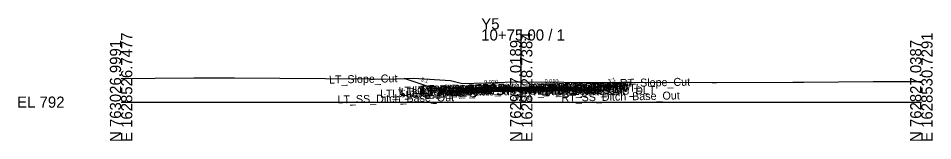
# Model space of a CAD drawing. Extents: x -26 to 203, y -10 to 6017.
# Drawn here: x -25.7 to 202.8, y 1490.3 to 1521.1 of the extents above; entities that cross this region are included whole.
import ezdxf

# ---------------------------------------------------------------- set-up
doc = ezdxf.new("R2010")
doc.units = 0
for name, color, linetype in [('Default', 7, 'Continuous'), ('Exist Cross Section Cell', 7, 'Continuous'), ('Exist XS Center Line Elevation Label', 7, 'Continuous'), ('Exist XS Ground Line', 7, 'Continuous'), ('Prop CMT Concrete Structures', 7, 'Continuous'), ('Prop CMT Pvmt Course 1', 7, 'Continuous'), ('Prop CMT Pvmt Course 2', 7, 'Continuous'), ('Prop CMT Pvmt Course 2 Wedge', 7, 'Continuous'), ('Prop CMT Pvmt Course 3', 7, 'Continuous'), ('Prop CMT Pvmt Course 3 Wedge', 7, 'Continuous'), ('Prop CMT Pvmt Surface', 7, 'Continuous'), ('Prop CMT Pvmt Surface Shoulder', 7, 'Continuous'), ('Prop CMT Pvmt Wedge Surface 2', 7, 'Continuous'), ('Prop CMT Pvmt Wedge Surface 3', 7, 'Continuous'), ('Prop CMT Shld Paved Course 1', 7, 'Continuous'), ('Prop CMT Shld Paved Course 2', 7, 'Continuous'), ('Prop CMT Shld Paved Course 3', 7, 'Continuous'), ('Prop CMT Slope Grass', 7, 'Continuous'), ('Prop CMT Subgrade Earthwork', 7, 'Continuous'), ('Prop XS SE Text', 7, 'Continuous'), ('Prop XS Side Slope Text', 7, 'Continuous'), ('Scratch_Level_0', 7, 'Continuous')]:
    doc.layers.add(name, color=color, linetype=linetype)

msp = doc.modelspace()

# ---------------------------------------------------------------- linework, layer by layer
at = {"layer": 'Exist Cross Section Cell'}
for p, q in [((100, 1500), (100, 1518.25)), ((0, 1500), (100, 1500)), ((100, 1500), (200, 1500))]:
    msp.add_line(p, q, dxfattribs=at)
at = {"layer": 'Exist XS Ground Line'}
msp.add_lwpolyline([(0, 1505.93), (8.51, 1505.99), (18.21, 1506.08), (28.36, 1506.08), (62.45, 1505.86), (66.74, 1505.79), (73.06, 1506.01), (82.35, 1505.39), (85.34, 1504.64), (91.08, 1504.83), (98.44, 1505.07), (100, 1505.06), (110.61, 1504.97), (114.33, 1504.92), (115.88, 1504.95), (124.96, 1505.01), (127.4, 1505.02), (147.74, 1504.96), (148.83, 1504.96), (167.92, 1504.98), (170.61, 1504.99), (187.96, 1505.15), (191.45, 1505.16), (200, 1505.2)], dxfattribs=at)
at = {"layer": 'Prop CMT Concrete Structures'}
for points in [[(115, 1503.29), (115, 1503.87)], [(117, 1503.87), (117, 1503.29), (115, 1503.29)], [(115, 1503.87), (116, 1503.79), (117, 1503.87)], [(83, 1503.42), (83, 1502.84), (85, 1502.84)], [(85, 1503.42), (84, 1503.34), (83, 1503.42)], [(85, 1502.84), (85, 1503.42)]]:
    msp.add_lwpolyline(points, dxfattribs=at)
at = {"layer": 'Prop CMT Pvmt Course 1'}
for points in [[(100, 1503.72), (115, 1503.87)], [(100, 1503.72), (114.33, 1503.86)], [(115, 1503.87), (115, 1503.62)], [(100, 1503.72), (85, 1503.42)], [(85, 1503.17), (100, 1503.47)], [(85, 1503.42), (85, 1503.17)], [(100, 1503.72), (85.32, 1503.43)], [(100, 1503.59), (100, 1503.72)], [(100, 1503.47), (100, 1503.72)], [(100, 1503.59), (100, 1503.72)], [(100, 1503.47), (100, 1503.72)], [(115, 1503.62), (100, 1503.47)]]:
    msp.add_lwpolyline(points, dxfattribs=at)
at = {"layer": 'Prop CMT Pvmt Course 2'}
for points in [[(100, 1503.47), (85, 1503.17)], [(85, 1503.17), (85, 1502.84)], [(85, 1502.84), (100, 1503.14)], [(100, 1503.47), (115, 1503.62)], [(100, 1503.14), (100, 1503.47)], [(100, 1503.14), (100, 1503.47)], [(115, 1503.29), (100, 1503.14)], [(115, 1503.62), (115, 1503.29)]]:
    msp.add_lwpolyline(points, dxfattribs=at)
at = {"layer": 'Prop CMT Pvmt Course 2 Wedge'}
for points in [[(100, 1503.47), (85.32, 1503.18)], [(100, 1503.47), (114.33, 1503.61)]]:
    msp.add_lwpolyline(points, dxfattribs=at)
at = {"layer": 'Prop CMT Pvmt Course 3'}
msp.add_line((117, 1503.29), (117.5, 1503.29), dxfattribs=at)
for points in [[(100, 1503.14), (85, 1502.84)], [(85, 1502.84), (85, 1502.5)], [(85, 1502.5), (100, 1502.8)], [(100, 1503.14), (115, 1503.29)], [(100, 1502.8), (100, 1503.14)], [(100, 1502.8), (100, 1503.14)], [(115, 1502.95), (100, 1502.8)], [(115, 1503.29), (115, 1502.95)]]:
    msp.add_lwpolyline(points, dxfattribs=at)
at = {"layer": 'Prop CMT Pvmt Course 3 Wedge'}
for points in [[(100, 1503.14), (85.32, 1502.84)], [(100, 1503.14), (114.33, 1503.28)]]:
    msp.add_lwpolyline(points, dxfattribs=at)
at = {"layer": 'Prop CMT Pvmt Surface'}
for points in [[(100, 1503.72), (115, 1503.87)], [(100, 1503.72), (114.33, 1503.86)], [(100, 1503.72), (85, 1503.42)], [(100, 1503.72), (85.32, 1503.43)]]:
    msp.add_lwpolyline(points, dxfattribs=at)
at = {"layer": 'Prop CMT Pvmt Surface Shoulder'}
for points in [[(115, 1503.87), (115, 1503.87)], [(85, 1503.42), (85, 1503.42)]]:
    msp.add_lwpolyline(points, dxfattribs=at)
at = {"layer": 'Prop CMT Pvmt Wedge Surface 2'}
for points in [[(100, 1503.47), (85.32, 1503.18)], [(100, 1503.47), (100, 1503.72)], [(100, 1503.47), (100, 1503.72)], [(100, 1503.47), (100, 1503.72)], [(100, 1503.47), (100, 1503.72)], [(100, 1503.47), (114.33, 1503.61)]]:
    msp.add_lwpolyline(points, dxfattribs=at)
at = {"layer": 'Prop CMT Pvmt Wedge Surface 3'}
for points in [[(100, 1503.14), (85.32, 1502.84)], [(100, 1503.14), (100, 1503.72)], [(100, 1503.14), (100, 1503.72)], [(100, 1503.14), (100, 1503.72)], [(100, 1503.14), (100, 1503.72)], [(100, 1503.14), (114.33, 1503.28)]]:
    msp.add_lwpolyline(points, dxfattribs=at)
at = {"layer": 'Prop CMT Shld Paved Course 1'}
for points in [[(115, 1503.87), (115, 1503.87)], [(115, 1503.62), (115, 1503.87)], [(85, 1503.42), (85, 1503.42)], [(85, 1503.17), (85, 1503.42)]]:
    msp.add_lwpolyline(points, dxfattribs=at)
at = {"layer": 'Prop CMT Shld Paved Course 2'}
for p, q in [((83, 1502.84), (85, 1502.84)), ((117, 1503.29), (115, 1503.29))]:
    msp.add_line(p, q, dxfattribs=at)
for points in [[(85, 1502.84), (85, 1503.17)], [(115, 1503.29), (115, 1503.62)]]:
    msp.add_lwpolyline(points, dxfattribs=at)
at = {"layer": 'Prop CMT Shld Paved Course 3'}
for p, q in [((82.16, 1502.5), (85, 1502.5)), ((117.84, 1502.95), (115, 1502.95))]:
    msp.add_line(p, q, dxfattribs=at)
for points in [[(85, 1502.84), (83, 1502.84), (82.5, 1502.84), (82.16, 1502.5)], [(85, 1502.5), (85, 1502.84)], [(115, 1503.29), (117.5, 1503.29), (117.5, 1503.29), (117.84, 1502.95)], [(115, 1502.95), (115, 1503.29)]]:
    msp.add_lwpolyline(points, dxfattribs=at)
at = {"layer": 'Prop CMT Slope Grass'}
for points in [[(83, 1503.42), (78, 1503.52), (70.78, 1505.93)], [(117, 1503.87), (122, 1503.97), (125.13, 1505.01)]]:
    msp.add_lwpolyline(points, dxfattribs=at)
at = {"layer": 'Prop CMT Subgrade Earthwork'}
for p, q in [((117.84, 1502.95), (118.8, 1503.91)), ((82.16, 1502.5), (81.2, 1503.46)), ((85, 1502.5), (82.16, 1502.5)), ((115, 1502.95), (117.84, 1502.95))]:
    msp.add_line(p, q, dxfattribs=at)
for points in [[(100, 1502.8), (85, 1502.5)], [(100, 1502.8), (115, 1502.95)]]:
    msp.add_lwpolyline(points, dxfattribs=at)

# ---------------------------------------------------------------- texts
at = {"layer": 'Default'}
msp.add_text('-', height=0.0001, dxfattribs=at).set_placement((0, 1500))
at = {"layer": 'Exist Cross Section Cell'}
for s, p in [('Y5', (90, 1518.25)), ('10+75.00 / 1', (90, 1515.45)), ('EL 792', (-26, 1498.6))]:
    msp.add_text(s, height=2.8, dxfattribs=at).set_placement(p)
for s, p in [('N 763026.9991', (0, 1490)), ('E 1628526.7477', (2.8, 1490)), ('N 762927.0189', (100, 1490)), ('E 1628528.7384', (102.8, 1490)), ('N 762827.0387', (200, 1490)), ('E 1628530.7291', (202.8, 1490))]:
    msp.add_text(s, height=2.8, rotation=90, dxfattribs=at).set_placement(p)
at = {"layer": 'Exist XS Center Line Elevation Label'}
msp.add_text('797.06', height=1.2, dxfattribs=at).set_placement((97.54, 1500.46))
at = {"layer": 'Prop XS SE Text'}
for s, rotation, p in [('0.020', 1.1458, (90.73, 1504.53)), ('0.010', 0.5729, (105.86, 1504.78))]:
    msp.add_text(s, height=1, rotation=rotation, dxfattribs=at).set_placement(p)
at = {"layer": 'Prop XS Side Slope Text'}
for rotation, p in [(341.5651, (74.8, 1505.32)), (18.4349, (121.85, 1504.71))]:
    msp.add_text('3:1', height=1, rotation=rotation, dxfattribs=at).set_placement(p)
at = {"layer": 'Scratch_Level_0'}
for s, p in [('LT_Slope_Cut', (51.98, 1504.65)), ('RT_Slope_Cut', (124.68, 1503.79)), ('LT_GS_OS_CTL', (69.39, 1501.81)), ('LT_PS3_Shelf_Out', (69.91, 1501.53)), ('LT_PV2_OEEOP_W', (72.76, 1501.92)), ('LT_PV3_OEEOP_W', (72.76, 1501.59)), ('LT_PV1_OEEOP_W', (73.33, 1502.06)), ('LT_PS3_OEOP', (74.66, 1501.63)), ('LT_PS2_OEOP', (75, 1501.97)), ('LT_PV2_OEOT', (75.2, 1501.97)), ('LT_PV3_OEOT', (75.2, 1501.64)), ('LT_PV1_OEEOP', (75.22, 1502.22)), ('LT_PV1_OEOT', (75.76, 1502.23)), ('LT_PS1_OEOP', (75.83, 1502.24)), ('RT_PV1_PGL_W', (89.86, 1502.39)), ('LT_PV1_PGL_W', (89.91, 1502.39)), ('Sub_PGL', (93.83, 1501.68)), ('PV2_PGL', (93.93, 1502.35)), ('PV3_PGL', (93.93, 1502.01)), ('PV1_PGL', (94.49, 1502.61)), ('RT_Sub_Trench_Out', (100.62, 1501.61)), ('RT_PV2_OEEOP_W', (101.72, 1502.36)), ('RT_PV3_OEEOP_W', (101.72, 1502.03)), ('RT_PS3_Shelf_Out', (102.06, 1501.98)), ('RT_PV1_OEEOP_W', (102.29, 1502.5)), ('RT_PV1_OEEOP', (104.18, 1502.66)), ('RT_Sub_OEOT', (105.05, 1501.75)), ('RT_PV2_OEOT', (105.15, 1502.42)), ('RT_PV3_OEOT', (105.15, 1502.09)), ('RT_PS2_OEOP', (105.47, 1502.42)), ('RT_PV1_OEOT', (105.71, 1502.68)), ('RT_PS1_OEOP', (105.78, 1502.68)), ('RT_PS3_OEOP', (105.81, 1502.08)), ('RT_GS_OS_CTL', (109.35, 1502.26)), ('RT_Sub_OSS_DLT', (110.06, 1501.55)), ('LT_SS_Ditch_Base_Out', (54.1, 1499.66)), ('LT_Sub_OSS_DLT', (64.74, 1501.1)), ('LT_Sub_Trench_Out', (67.79, 1501.16)), ('LT_Sub_OEOT', (75.1, 1501.3)), ('RT_SS_Ditch_Base_Out', (110.06, 1500.11))]:
    msp.add_text(s, height=2, rotation=1.1458, dxfattribs=at).set_placement(p)

doc.saveas('drawing.dxf')
